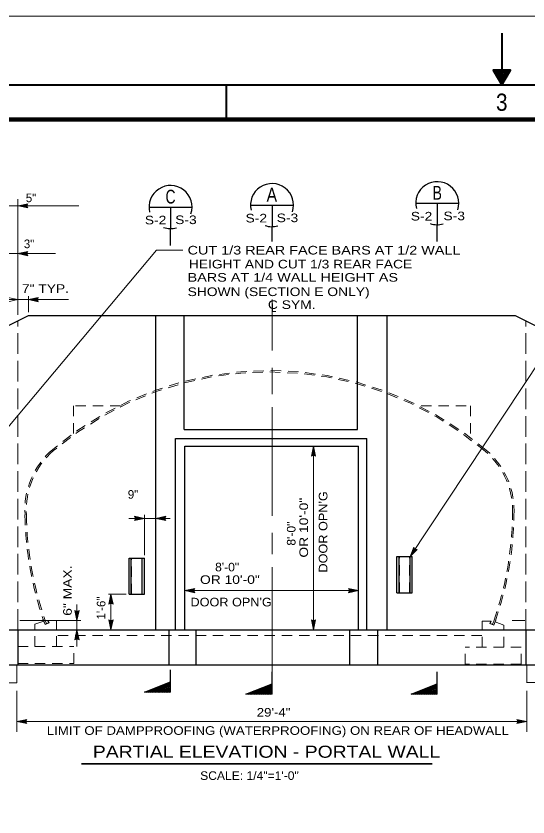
# Model space of a CAD drawing. Extents: x -22.3 to 19.7, y -11.8 to 18.2.
# Drawn here: x -8.36 to -0.93, y 6.54 to 18.16 of the extents above; entities that cross this region are included whole.
import ezdxf
from ezdxf.enums import TextEntityAlignment as Align

# ---------------------------------------------------------------- set-up
doc = ezdxf.new("R2010")
doc.units = 0
doc.header["$LTSCALE"] = 0.05
doc.linetypes.add('LONG_DASHED', pattern=[7.5, 6, -1.5])
doc.linetypes.add('MEDIUM_DASHED', pattern=[4.5, 3, -1.5])
doc.layers.add('1', color=7, linetype='Continuous', lineweight=13)
doc.layers.add('2', color=7, linetype='Continuous', lineweight=13)

msp = doc.modelspace()

# ---------------------------------------------------------------- linework, layer by layer
at = {"layer": '1', "lineweight": 40}
for p, q in [((-1.30942, 17.91031), (-1.30942, 17.16031)), ((-5.30942, 17.16031), (-5.30942, 16.66031))]:
    msp.add_line(p, q, dxfattribs=at)
at = {"layer": '1'}
for p, q in [((-8.33342, 13.82531), (-8.33342, 15.50531)), ((-8.32942, 15.40731), (-8.18542, 15.43831)), ((-8.32942, 15.40731), (-8.18542, 15.37631)), ((-8.29242, 15.40731), (-8.19842, 15.42731)), ((-8.29242, 15.40731), (-8.19842, 15.38731)), ((-8.25642, 15.40731), (-8.21142, 15.41731)), ((-8.25642, 15.40731), (-8.21142, 15.39831)), ((-8.21142, 15.41731), (-8.21542, 15.40731)), ((-8.21542, 15.40731), (-8.21142, 15.39831)), ((-8.19842, 15.42731), (-8.20742, 15.40731)), ((-8.20742, 15.40731), (-8.19842, 15.38731)), ((-8.33342, 14.71431), (-8.18942, 14.74531)), ((-8.33342, 14.71431), (-8.18942, 14.68331)), ((-8.29642, 14.71431), (-8.20242, 14.73431)), ((-8.29642, 14.71431), (-8.20242, 14.69431)), ((-8.26042, 14.71431), (-8.21542, 14.72431)), ((-8.26042, 14.71431), (-8.21542, 14.70531)), ((-8.21542, 14.72431), (-8.21942, 14.71431)), ((-8.21942, 14.71431), (-8.21542, 14.70531)), ((-8.20242, 14.73431), (-8.21142, 14.71431)), ((-8.21142, 14.71431), (-8.20242, 14.69431)), ((-8.33342, 14.04631), (-8.47742, 14.07731)), ((-8.17942, 13.86431), (-8.17942, 14.09731)), ((-8.17942, 14.04631), (-8.03542, 14.07731)), ((-8.14242, 14.04631), (-8.04842, 14.06631)), ((-8.04842, 14.06631), (-8.05742, 14.04631)), ((-8.53242, 14.04631), (-8.33342, 14.04631)), ((-8.33342, 14.04631), (-8.47742, 14.01531)), ((-8.17942, 14.04631), (-8.03542, 14.01531)), ((-8.14242, 14.04631), (-8.04842, 14.02631)), ((-8.10642, 14.04631), (-8.06142, 14.05631)), ((-8.10642, 14.04631), (-8.06142, 14.03731)), ((-8.06142, 14.05631), (-8.06542, 14.04631)), ((-8.06542, 14.04631), (-8.06142, 14.03731)), ((-8.05742, 14.04631), (-8.04842, 14.02631)), ((-4.64342, 13.31031), (-4.64342, 14.04931)), ((-4.64342, 12.67731), (-4.64342, 13.05731)), ((-4.64342, 10.91231), (-4.64342, 12.48731)), ((-4.04142, 11.91931), (-4.07242, 11.77531)), ((-4.04142, 11.88231), (-4.06142, 11.78831)), ((-4.04142, 9.25831), (-4.04142, 11.91931)), ((-4.04142, 11.91931), (-4.01042, 11.77531)), ((-4.04142, 11.88231), (-4.02142, 11.78831)), ((-4.04142, 11.79731), (-4.06142, 11.78831)), ((-4.04142, 11.84631), (-4.05042, 11.80131)), ((-4.04142, 11.80531), (-4.05042, 11.80131)), ((-4.04142, 11.84631), (-4.03142, 11.80131)), ((-4.03142, 11.80131), (-4.04142, 11.80531)), ((-4.02142, 11.78831), (-4.04142, 11.79731)), ((-6.49542, 10.33831), (-6.49542, 10.92331)), ((-6.49442, 10.87331), (-6.63842, 10.90431)), ((-6.49442, 10.87331), (-6.63842, 10.84231)), ((-6.53142, 10.87331), (-6.62542, 10.89331)), ((-6.61642, 10.87331), (-6.62542, 10.89331)), ((-6.53142, 10.87331), (-6.62542, 10.85331)), ((-6.62542, 10.85331), (-6.61642, 10.87331)), ((-6.56742, 10.87331), (-6.61242, 10.88231)), ((-6.60842, 10.87331), (-6.61242, 10.88231)), ((-6.56742, 10.87331), (-6.61242, 10.86331)), ((-6.61242, 10.86331), (-6.60842, 10.87331)), ((-6.32942, 10.87331), (-6.18542, 10.90431)), ((-6.32942, 10.87331), (-6.18542, 10.84231)), ((-6.29242, 10.87331), (-6.19842, 10.89331)), ((-6.29242, 10.87331), (-6.19842, 10.85331)), ((-6.25642, 10.87331), (-6.21142, 10.88331)), ((-6.25642, 10.87331), (-6.21142, 10.86431)), ((-6.21142, 10.88331), (-6.21542, 10.87331)), ((-6.21542, 10.87331), (-6.21142, 10.86431)), ((-6.19842, 10.89331), (-6.20742, 10.87331)), ((-6.20742, 10.87331), (-6.19842, 10.85331)), ((-4.64342, 10.35431), (-4.64342, 10.66631)), ((-2.64042, 10.32031), (-2.58642, 10.45731)), ((-2.64042, 10.32031), (-2.53542, 10.42331)), ((-2.62042, 10.35131), (-2.58442, 10.44031)), ((-2.62042, 10.35131), (-2.55142, 10.41831)), ((-2.60042, 10.38131), (-2.58342, 10.42431)), ((-2.60042, 10.38131), (-2.56742, 10.41331)), ((-2.58442, 10.44031), (-2.57342, 10.42231)), ((-2.58342, 10.42431), (-2.57742, 10.41531)), ((-2.57742, 10.41531), (-2.56742, 10.41331)), ((-2.57342, 10.42231), (-2.55142, 10.41831)), ((-4.64342, 8.45031), (-4.64342, 10.16631)), ((-6.76142, 9.77431), (-7.01642, 9.77431)), ((-6.98042, 9.77531), (-7.01142, 9.63131)), ((-6.98042, 9.25831), (-6.98042, 9.77531)), ((-6.98042, 9.77531), (-6.94942, 9.63131)), ((-5.90742, 9.82731), (-5.76342, 9.85831)), ((-5.90742, 9.82731), (-3.38742, 9.82731)), ((-5.90742, 9.82731), (-5.76342, 9.79631)), ((-5.87042, 9.82731), (-5.77642, 9.84731)), ((-5.87042, 9.82731), (-5.77642, 9.80731)), ((-5.83442, 9.82731), (-5.78942, 9.83731)), ((-5.83442, 9.82731), (-5.78942, 9.81831)), ((-5.78942, 9.83731), (-5.79342, 9.82731)), ((-5.79342, 9.82731), (-5.78942, 9.81831)), ((-5.77642, 9.84731), (-5.78542, 9.82731)), ((-5.78542, 9.82731), (-5.77642, 9.80731)), ((-3.38742, 9.82731), (-3.53142, 9.85831)), ((-3.38742, 9.82731), (-3.53142, 9.79631)), ((-3.42442, 9.82731), (-3.51842, 9.84731)), ((-3.50942, 9.82731), (-3.51842, 9.84731)), ((-3.42442, 9.82731), (-3.51842, 9.80731)), ((-3.51842, 9.80731), (-3.50942, 9.82731)), ((-3.46042, 9.82731), (-3.50542, 9.83631)), ((-3.50142, 9.82731), (-3.50542, 9.83631)), ((-3.46042, 9.82731), (-3.50542, 9.81731)), ((-3.50542, 9.81731), (-3.50142, 9.82731)), ((-6.98042, 9.73831), (-7.00042, 9.64431)), ((-6.98042, 9.65331), (-7.00042, 9.64431)), ((-6.98042, 9.70231), (-6.98942, 9.65731)), ((-6.98042, 9.66131), (-6.98942, 9.65731)), ((-6.98042, 9.73831), (-6.96042, 9.64431)), ((-6.98042, 9.70231), (-6.97042, 9.65731)), ((-6.97042, 9.65731), (-6.98042, 9.66131)), ((-6.96042, 9.64431), (-6.98042, 9.65331)), ((-7.47442, 9.39231), (-7.50542, 9.53631)), ((-7.47442, 9.39231), (-7.44342, 9.53631)), ((-7.47442, 9.42931), (-7.49442, 9.52331)), ((-7.49442, 9.52331), (-7.47442, 9.51431)), ((-7.47442, 9.46531), (-7.48442, 9.51031)), ((-7.48442, 9.51031), (-7.47442, 9.50631)), ((-7.47442, 9.42931), (-7.45442, 9.52331)), ((-7.47442, 9.51431), (-7.45442, 9.52331)), ((-7.47442, 9.46531), (-7.46542, 9.51031)), ((-7.47442, 9.50631), (-7.46542, 9.51031)), ((-8.30442, 9.39231), (-7.41742, 9.39231)), ((-6.98042, 9.25831), (-7.01142, 9.40231)), ((-6.98042, 9.29531), (-7.00042, 9.38931)), ((-7.00042, 9.38931), (-6.98042, 9.38031)), ((-6.98042, 9.33131), (-6.99042, 9.37631)), ((-6.99042, 9.37631), (-6.98042, 9.37231)), ((-6.98042, 9.25831), (-6.94942, 9.40231)), ((-6.98042, 9.29531), (-6.96042, 9.38931)), ((-6.98042, 9.38031), (-6.96042, 9.38931)), ((-6.98042, 9.33131), (-6.97142, 9.37631)), ((-6.98042, 9.37231), (-6.97142, 9.37631)), ((-4.04142, 9.25831), (-4.07242, 9.40231)), ((-4.04142, 9.29531), (-4.06142, 9.38931)), ((-4.06142, 9.38931), (-4.04142, 9.38031)), ((-4.04142, 9.33131), (-4.05142, 9.37631)), ((-4.05142, 9.37631), (-4.04142, 9.37231)), ((-4.04142, 9.25831), (-4.01042, 9.40231)), ((-4.04142, 9.29531), (-4.02142, 9.38931)), ((-4.04142, 9.38031), (-4.02142, 9.38931)), ((-4.04142, 9.33131), (-4.03242, 9.37631)), ((-4.04142, 9.37231), (-4.03242, 9.37631)), ((-1.15942, 9.39231), (-0.97542, 9.39231)), ((-7.47442, 9.25831), (-7.50542, 9.11431)), ((-7.47442, 9.22131), (-7.49442, 9.12731)), ((-7.47442, 9.18531), (-7.48342, 9.14031)), ((-7.47442, 9.25831), (-7.44342, 9.11431)), ((-7.47442, 9.22131), (-7.45442, 9.12731)), ((-7.47442, 9.18531), (-7.46442, 9.14031)), ((-7.47442, 9.13631), (-7.49442, 9.12731)), ((-7.47442, 9.14431), (-7.48342, 9.14031)), ((-7.46442, 9.14031), (-7.47442, 9.14431)), ((-7.45442, 9.12731), (-7.47442, 9.13631)), ((-8.34742, 8.37131), (-8.34742, 7.77731)), ((-0.94442, 8.37131), (-0.94442, 7.77731)), ((-8.34742, 7.92831), (-8.20342, 7.95931)), ((-8.34742, 7.92831), (-0.94442, 7.92831)), ((-8.34742, 7.92831), (-8.20342, 7.89731)), ((-8.31042, 7.92831), (-8.21642, 7.94831)), ((-8.31042, 7.92831), (-8.21642, 7.90831)), ((-8.27442, 7.92831), (-8.22942, 7.93831)), ((-8.27442, 7.92831), (-8.22942, 7.91931)), ((-8.22942, 7.93831), (-8.23342, 7.92831)), ((-8.23342, 7.92831), (-8.22942, 7.91931)), ((-8.21642, 7.94831), (-8.22542, 7.92831)), ((-8.22542, 7.92831), (-8.21642, 7.90831)), ((-0.94442, 7.92831), (-1.08842, 7.95931)), ((-0.94442, 7.92831), (-1.08842, 7.89731)), ((-0.98142, 7.92831), (-1.07542, 7.94831)), ((-1.06642, 7.92831), (-1.07542, 7.94831)), ((-0.98142, 7.92831), (-1.07542, 7.90831)), ((-1.07542, 7.90831), (-1.06642, 7.92831)), ((-1.01742, 7.92831), (-1.06242, 7.93731)), ((-1.05842, 7.92831), (-1.06242, 7.93731)), ((-1.01742, 7.92831), (-1.06242, 7.91831)), ((-1.06242, 7.91831), (-1.05842, 7.92831))]:
    msp.add_line(p, q, dxfattribs=at)
at = {"layer": '1', "linetype": 'LONG_DASHED'}
for p, q in [((-8.33342, 9.25831), (-8.33342, 13.72931)), ((-0.95842, 9.25831), (-0.95842, 13.73231)), ((-8.34742, 8.74831), (-8.34742, 8.49031)), ((-0.94442, 8.74831), (-0.94442, 8.49031)), ((-17.03142, 8.49031), (-8.34742, 8.49031)), ((-0.94442, 8.49131), (1.83058, 8.49131))]:
    msp.add_line(p, q, dxfattribs=at)
at = {"layer": '1', "lineweight": 25}
for p, q in [((-6.32942, 9.25831), (-6.32942, 13.81631)), ((-5.91642, 12.16231), (-5.91642, 13.81631)), ((-3.40242, 12.16231), (-3.40242, 13.81631)), ((-2.97042, 9.25831), (-2.97042, 13.81631)), ((-5.91642, 12.16231), (-3.40242, 12.16231)), ((-6.04242, 9.25831), (-6.04242, 12.03131)), ((-6.04242, 12.03131), (-3.26742, 12.03131)), ((-3.26742, 9.25831), (-3.26742, 12.03131)), ((-5.90742, 9.25831), (-5.90742, 11.92031)), ((-5.90742, 11.91931), (-3.38742, 11.91931)), ((-3.38742, 9.25831), (-3.38742, 11.92031)), ((-6.71742, 9.77431), (-6.71742, 10.29831)), ((-6.71742, 10.29831), (-6.49542, 10.29831)), ((-6.68742, 9.77431), (-6.68742, 10.29831)), ((-6.52742, 9.77431), (-6.52742, 10.29831)), ((-6.49542, 9.77431), (-6.49542, 10.29831)), ((-2.83042, 9.79631), (-2.83042, 10.32031)), ((-2.83042, 10.32031), (-2.60842, 10.32031)), ((-2.80042, 9.79631), (-2.80042, 10.32031)), ((-2.64042, 9.79631), (-2.64042, 10.32031)), ((-2.60842, 9.79631), (-2.60842, 10.32031)), ((-6.71742, 9.77431), (-6.49542, 9.77431)), ((-2.83042, 9.79631), (-2.60842, 9.79631)), ((-8.33342, 9.25831), (-8.33342, 8.74831)), ((-6.13742, 8.74831), (-6.13742, 9.25831)), ((-5.74642, 8.74831), (-5.74642, 9.25831)), ((-3.51442, 8.74831), (-3.51442, 9.25831)), ((-3.10942, 8.74831), (-3.10942, 9.25831)), ((-0.95842, 9.25831), (-0.95842, 8.74831)), ((-17.03142, 8.74831), (1.83058, 8.74831))]:
    msp.add_line(p, q, dxfattribs=at)
at = {"layer": '1', "linetype": 'MEDIUM_DASHED'}
for p, q in [((-6.68042, 9.77431), (-6.68042, 10.29831)), ((-6.53442, 9.77431), (-6.53442, 10.29831)), ((-2.79342, 9.79631), (-2.79342, 10.32031)), ((-2.64742, 9.79631), (-2.64742, 10.32031)), ((-7.95742, 9.38131), (-8.08342, 9.33731)), ((-8.08342, 9.01731), (-8.08342, 9.33731)), ((-7.96842, 9.40731), (-7.96542, 9.40931)), ((-7.96842, 9.40731), (-7.93742, 9.33431)), ((-7.96542, 9.40931), (-7.93542, 9.33931)), ((-7.87942, 9.35931), (-7.93742, 9.33431)), ((-7.93542, 9.39331), (-7.91642, 9.34831)), ((-7.89742, 9.39031), (-7.89442, 9.39231)), ((-7.89442, 9.39231), (-7.87942, 9.35931)), ((-7.89442, 9.39231), (-7.77042, 9.39231)), ((-7.77042, 9.01731), (-7.77042, 9.39231)), ((-1.59142, 9.00731), (-1.59142, 9.38231)), ((-1.46742, 9.38231), (-1.59142, 9.38231)), ((-1.46742, 9.38231), (-1.48242, 9.34931)), ((-1.48242, 9.34931), (-1.42442, 9.32431)), ((-1.46442, 9.38031), (-1.46742, 9.38231)), ((-1.42642, 9.38331), (-1.44542, 9.33831)), ((-1.39642, 9.39931), (-1.42642, 9.32931)), ((-1.39342, 9.39731), (-1.42442, 9.32431)), ((-1.40442, 9.37131), (-1.27842, 9.32731)), ((-1.39342, 9.39731), (-1.39642, 9.39931)), ((-1.27842, 9.00731), (-1.27842, 9.32731)), ((-7.75042, 9.17731), (-1.57042, 9.17731)), ((-8.33342, 8.76731), (-8.33342, 9.01731)), ((-8.33342, 9.01731), (-7.52042, 9.01731)), ((-7.52042, 8.76731), (-7.52042, 9.01731)), ((-1.84142, 8.75731), (-1.84142, 9.00731)), ((-1.02842, 9.00731), (-1.84142, 9.00731)), ((-1.02842, 8.75731), (-1.02842, 9.00731)), ((-8.33342, 8.76731), (-7.52042, 8.76731)), ((-1.02842, 8.75731), (-1.84142, 8.75731))]:
    msp.add_line(p, q, dxfattribs=at)
at = {"layer": '1', "lineweight": 35}
msp.add_line((-7.40842, 7.31531), (-2.31842, 7.31531), dxfattribs=at)
at = {"layer": '1'}
for points in [[(-22.30942, 18.16031), (19.69058, 18.16031), (19.69058, -11.83969)], [(-18.06742, 15.40731), (-17.03142, 15.40731), (-16.93242, 15.40731), (-10.43842, 15.40731), (-10.30242, 15.40731), (-8.44242, 15.40731), (-8.32942, 15.40731), (-7.44542, 15.40731)], [(-8.18542, 15.43831), (-8.19942, 15.40731), (-8.18542, 15.37631)], [(-9.28542, 11.23331), (-6.31842, 14.76331), (-5.93842, 14.76331)], [(-18.10442, 14.71431), (-17.03142, 14.71431), (-16.93242, 14.71431), (-14.20242, 14.71431), (-13.95142, 14.71431), (-12.68842, 14.71431), (-12.43842, 14.71431), (-11.43942, 14.71431), (-11.31142, 14.71431), (-10.43842, 14.71431), (-10.30342, 14.71431), (-9.17242, 14.71431), (-9.07942, 14.71431), (-8.44242, 14.71431), (-8.33342, 14.71431), (-7.78542, 14.71431)], [(-8.18942, 14.74531), (-8.20342, 14.71431), (-8.18942, 14.68331)], [(-8.03542, 14.07731), (-8.04942, 14.04631), (-8.03542, 14.01531)], [(-8.33342, 14.04631), (-8.17942, 14.04631), (-7.59942, 14.04631)], [(-2.64042, 10.32031), (-0.19342, 14.00631), (0.19158, 14.00631)], [(-4.01042, 11.77531), (-4.04142, 11.78931), (-4.07242, 11.77531)], [(-6.72142, 10.87331), (-6.49442, 10.87331), (-6.32942, 10.87331), (-6.12042, 10.87331)], [(-6.63842, 10.84231), (-6.62442, 10.87331), (-6.63842, 10.90431)], [(-6.18542, 10.90431), (-6.19942, 10.87331), (-6.18542, 10.84231)], [(-2.58642, 10.45731), (-2.56842, 10.42831), (-2.53542, 10.42331)], [(-5.76342, 9.85831), (-5.77742, 9.82731), (-5.76342, 9.79631)], [(-3.53142, 9.79631), (-3.51742, 9.82731), (-3.53142, 9.85831)], [(-6.94942, 9.63131), (-6.98042, 9.64531), (-7.01142, 9.63131)], [(-7.50542, 9.53631), (-7.47442, 9.52231), (-7.44342, 9.53631)], [(-7.47442, 9.01431), (-7.47442, 9.25831), (-7.47442, 9.39231), (-7.47442, 9.62331)], [(-7.01142, 9.40231), (-6.98042, 9.38831), (-6.94942, 9.40231)], [(-4.07242, 9.40231), (-4.04142, 9.38831), (-4.01042, 9.40231)], [(-7.44342, 9.11431), (-7.47442, 9.12831), (-7.50542, 9.11431)], [(-8.20342, 7.95931), (-8.21742, 7.92831), (-8.20342, 7.89731)], [(-1.08842, 7.89731), (-1.07442, 7.92831), (-1.08842, 7.95931)]]:
    msp.add_lwpolyline(points, dxfattribs=at)
at = {"layer": '1', "lineweight": 40}
for points in [[(-1.30942, 17.16031), (-1.18442, 17.37631), (-1.43442, 17.37631)], [(-21.30942, -10.83969), (-21.30942, 17.16031), (18.69058, 17.16031), (18.69058, -10.83969)]]:
    msp.add_lwpolyline(points, close=True, dxfattribs=at)
for points in [[(-1.30842, 17.20331), (-1.21942, 17.35531), (-1.39742, 17.35531), (-1.30942, 17.20331)], [(-1.30942, 17.24231), (-1.25642, 17.33531), (-1.36142, 17.33531), (-1.30742, 17.24131)], [(-1.30942, 17.28431), (-1.29242, 17.31431), (-1.32542, 17.31431), (-1.31042, 17.28831)]]:
    msp.add_lwpolyline(points, dxfattribs=at)
at = {"layer": '1', "lineweight": 90}
msp.add_lwpolyline([(-19.80942, 16.66031), (18.19058, 16.66031), (18.19058, -10.33969), (-19.80942, -10.33969)], close=True, dxfattribs=at)
at = {"layer": '1', "lineweight": 25}
for points in [[(-17.03142, 8.74831), (-17.03142, 9.37931), (-8.17942, 13.81631), (-1.11242, 13.81631), (1.83058, 12.34331)], [(-17.03142, 9.07131), (-10.35942, 9.07131), (-10.35942, 9.25831), (1.04358, 9.25831), (1.04358, 9.08631)]]:
    msp.add_lwpolyline(points, dxfattribs=at)
at = {"layer": '1', "linetype": 'MEDIUM_DASHED'}
for points in [[(-6.84442, 12.50531), (-7.52542, 12.50531), (-7.52542, 12.06731)], [(-2.47742, 12.50531), (-1.76142, 12.50531), (-1.76142, 12.06731)], [(-7.89742, 9.39031), (-7.88542, 9.36131), (-7.93542, 9.33931)], [(-1.46442, 9.38031), (-1.47642, 9.35131), (-1.42642, 9.32931)]]:
    msp.add_lwpolyline(points, dxfattribs=at)
for centre, radius, start, end in [((-4.6866, 8.14431), 4.87482, 49.71979, 130.09764), ((-4.6866, 8.14431), 4.85409, 49.71979, 130.09764), ((-7.0824, 10.99843), 1.14838, 130.38466, 183.72825), ((-7.0824, 10.99843), 1.12773, 130.38466, 183.72825), ((-2.27893, 10.98843), 1.14838, 356.27175, 49.61534), ((-2.27893, 10.98843), 1.12773, 356.27175, 49.61534), ((-3.35429, 10.99843), 4.87492, 180.86487, 199.33073), ((-3.35429, 10.99843), 4.85419, 180.86487, 199.33073), ((-6.00704, 10.98843), 4.85419, 340.66927, 359.13513), ((-6.00704, 10.98843), 4.87492, 340.66927, 359.13513)]:
    msp.add_arc(centre, radius, start, end, dxfattribs=at)
at = {"layer": '2', "lineweight": 25}
for p, q in [((-6.42842, 15.38931), (-5.80442, 15.38931)), ((-6.11642, 15.38931), (-6.11642, 15.07731)), ((-4.95542, 15.41731), (-4.33142, 15.41731)), ((-4.64342, 15.41731), (-4.64342, 15.10531)), ((-2.55742, 15.44531), (-1.93342, 15.44531)), ((-2.24542, 15.44531), (-2.24542, 15.13331)), ((-4.64342, 14.89131), (-4.64342, 15.10531)), ((-2.24542, 14.89131), (-2.24542, 15.13331)), ((-6.11642, 14.83431), (-6.11642, 15.07731)), ((-6.11642, 8.35531), (-6.11642, 8.67931)), ((-4.64342, 8.32631), (-4.64342, 8.65031)), ((-2.24542, 8.32631), (-2.24542, 8.65031)), ((-6.46442, 8.35531), (-6.11642, 8.49331)), ((-6.43142, 8.35531), (-6.11642, 8.48031)), ((-6.40842, 8.35531), (-6.11642, 8.47131)), ((-6.37242, 8.35531), (-6.11642, 8.45731)), ((-6.33842, 8.35531), (-6.11642, 8.44331)), ((-6.29742, 8.35531), (-6.11642, 8.42731)), ((-6.27042, 8.35531), (-6.11642, 8.41631)), ((-6.23842, 8.35531), (-6.11642, 8.40431)), ((-6.20942, 8.35531), (-6.11642, 8.39231)), ((-6.18042, 8.35531), (-6.11642, 8.38131)), ((-6.16042, 8.35531), (-6.11642, 8.37331)), ((-4.99142, 8.32631), (-4.64342, 8.46431)), ((-4.95842, 8.32631), (-4.64342, 8.45131)), ((-4.93542, 8.32631), (-4.64342, 8.44231)), ((-4.89942, 8.32631), (-4.64342, 8.42831)), ((-4.86542, 8.32631), (-4.64342, 8.41431)), ((-4.82442, 8.32631), (-4.64342, 8.39831)), ((-4.79742, 8.32631), (-4.64342, 8.38731)), ((-4.76542, 8.32631), (-4.64342, 8.37531)), ((-2.59342, 8.32631), (-2.24542, 8.46431)), ((-2.56042, 8.32631), (-2.24542, 8.45131)), ((-2.53742, 8.32631), (-2.24542, 8.44231)), ((-2.50142, 8.32631), (-2.24542, 8.42831)), ((-2.46742, 8.32631), (-2.24542, 8.41431)), ((-2.42642, 8.32631), (-2.24542, 8.39831)), ((-2.39942, 8.32631), (-2.24542, 8.38731)), ((-2.36742, 8.32631), (-2.24542, 8.37531)), ((-6.13342, 8.35531), (-6.11642, 8.36231)), ((-4.73642, 8.32631), (-4.64342, 8.36331)), ((-4.70742, 8.32631), (-4.64342, 8.35231)), ((-4.68742, 8.32631), (-4.64342, 8.34431)), ((-4.66042, 8.32631), (-4.64342, 8.33331)), ((-2.33842, 8.32631), (-2.24542, 8.36331)), ((-2.30942, 8.32631), (-2.24542, 8.35231)), ((-2.28942, 8.32631), (-2.24542, 8.34431)), ((-2.26242, 8.32631), (-2.24542, 8.33331))]:
    msp.add_line(p, q, dxfattribs=at)
for points in [[(-6.11642, 8.35531), (-6.49542, 8.35531), (-6.11642, 8.50531)], [(-4.64342, 8.32631), (-5.02242, 8.32631), (-4.64342, 8.47631)], [(-2.24542, 8.32631), (-2.62442, 8.32631), (-2.24542, 8.47631)]]:
    msp.add_lwpolyline(points, dxfattribs=at)
for centre, start, end in [((-6.11642, 15.38931), 341.96976, 193.81208), ((-4.64342, 15.41731), 341.96976, 193.81208), ((-2.24542, 15.44531), 341.96976, 193.81208), ((-4.64342, 15.41731), 251.04049, 285.74671), ((-2.24542, 15.44531), 251.04049, 285.74671), ((-6.11642, 15.38931), 251.04049, 285.74671)]:
    msp.add_arc(centre, 0.3125, start, end, dxfattribs=at)

# ---------------------------------------------------------------- texts
at = {"layer": '1'}
for s, height, width, p in [('3', 0.25, 0.9, (-1.30892, 16.78531)), ('C SYM.', 0.125, 1.2, (-4.35742, 13.91131)), ('29\'-4"', 0.125, 1.15, (-4.62042, 7.99831)), ('LIMIT OF DAMPPROOFING (WATERPROOFING) ON REAR OF HEADWALL', 0.125, 1.15, (-4.55842, 7.73431)), ('PARTIAL ELEVATION - PORTAL WALL', 0.175, 1.2, (-4.72292, 7.40231)), ('SCALE: 1/4"=1\'-0"', 0.125, 1.05, (-4.97092, 7.08031))]:
    msp.add_text(s, height=height, dxfattribs=dict(at, width=width)).set_placement(p, align=Align.CENTER)
for s, p in [('5"', (-8.21742, 15.46031)), ('3"', (-8.24542, 14.79331))]:
    msp.add_text(s, height=0.125, dxfattribs=at).set_placement(p)
for s, width, p in [('CUT 1/3 REAR FACE BARS AT 1/2 WALL', 1.25, (-5.86842, 14.70131)), ('HEIGHT AND CUT 1/3 REAR FACE', 1.2, (-5.85142, 14.49931)), ('BARS AT 1/4 WALL HEIGHT AS', 1.25, (-5.86842, 14.30731)), ('7" TYP.', 1.2, (-8.27342, 14.14531)), ('SHOWN (SECTION E ONLY)', 1.2, (-5.86842, 14.09831)), ('L', 0.75, (-4.65042, 13.86731)), ('8\'-0"', 1.05, (-5.46942, 10.10531)), ('OR 10\'-0"', 1.2, (-5.68842, 9.92331)), ("DOOR OPN'G", 1.1, (-5.82642, 9.59731))]:
    msp.add_text(s, height=0.125, dxfattribs=dict(at, width=width)).set_placement(p)
msp.add_text('9"', height=0.125, dxfattribs=at).set_placement((-6.66042, 11.15931), align=Align.CENTER)
for s, width, p in [('OR 10\'-0"', 1.2, (-4.12042, 10.30531)), ("DOOR OPN'G", 1.1, (-3.83942, 10.08831)), ('8\'-0"', 1.05, (-4.30242, 10.47831)), ('6" MAX.', 1.2, (-7.54942, 9.46131))]:
    msp.add_text(s, height=0.125, rotation=90, dxfattribs=dict(at, width=width)).set_placement(p)
msp.add_text('1\'-6"', height=0.125, rotation=90, dxfattribs=at).set_placement((-7.06142, 9.40731))
at = {"layer": '2'}
for s, height, width, p in [('B', 0.2, 0.75, (-2.24492, 15.49631)), ('C', 0.2, 0.75, (-6.11642, 15.44031)), ('A', 0.2, 0.85, (-4.64642, 15.46831)), ('S-2', 0.125, 1.2, (-6.33342, 15.13831)), ('S-3', 0.125, 1.2, (-5.89242, 15.14231)), ('S-2', 0.125, 1.2, (-4.87142, 15.16631)), ('S-3', 0.125, 1.2, (-4.41942, 15.17031)), ('S-2', 0.125, 1.2, (-2.47342, 15.19431)), ('S-3', 0.125, 1.2, (-1.99942, 15.19831))]:
    msp.add_text(s, height=height, dxfattribs=dict(at, width=width)).set_placement(p, align=Align.CENTER)

doc.saveas('drawing.dxf')
